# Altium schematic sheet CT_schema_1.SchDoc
size 381 x 258 mm
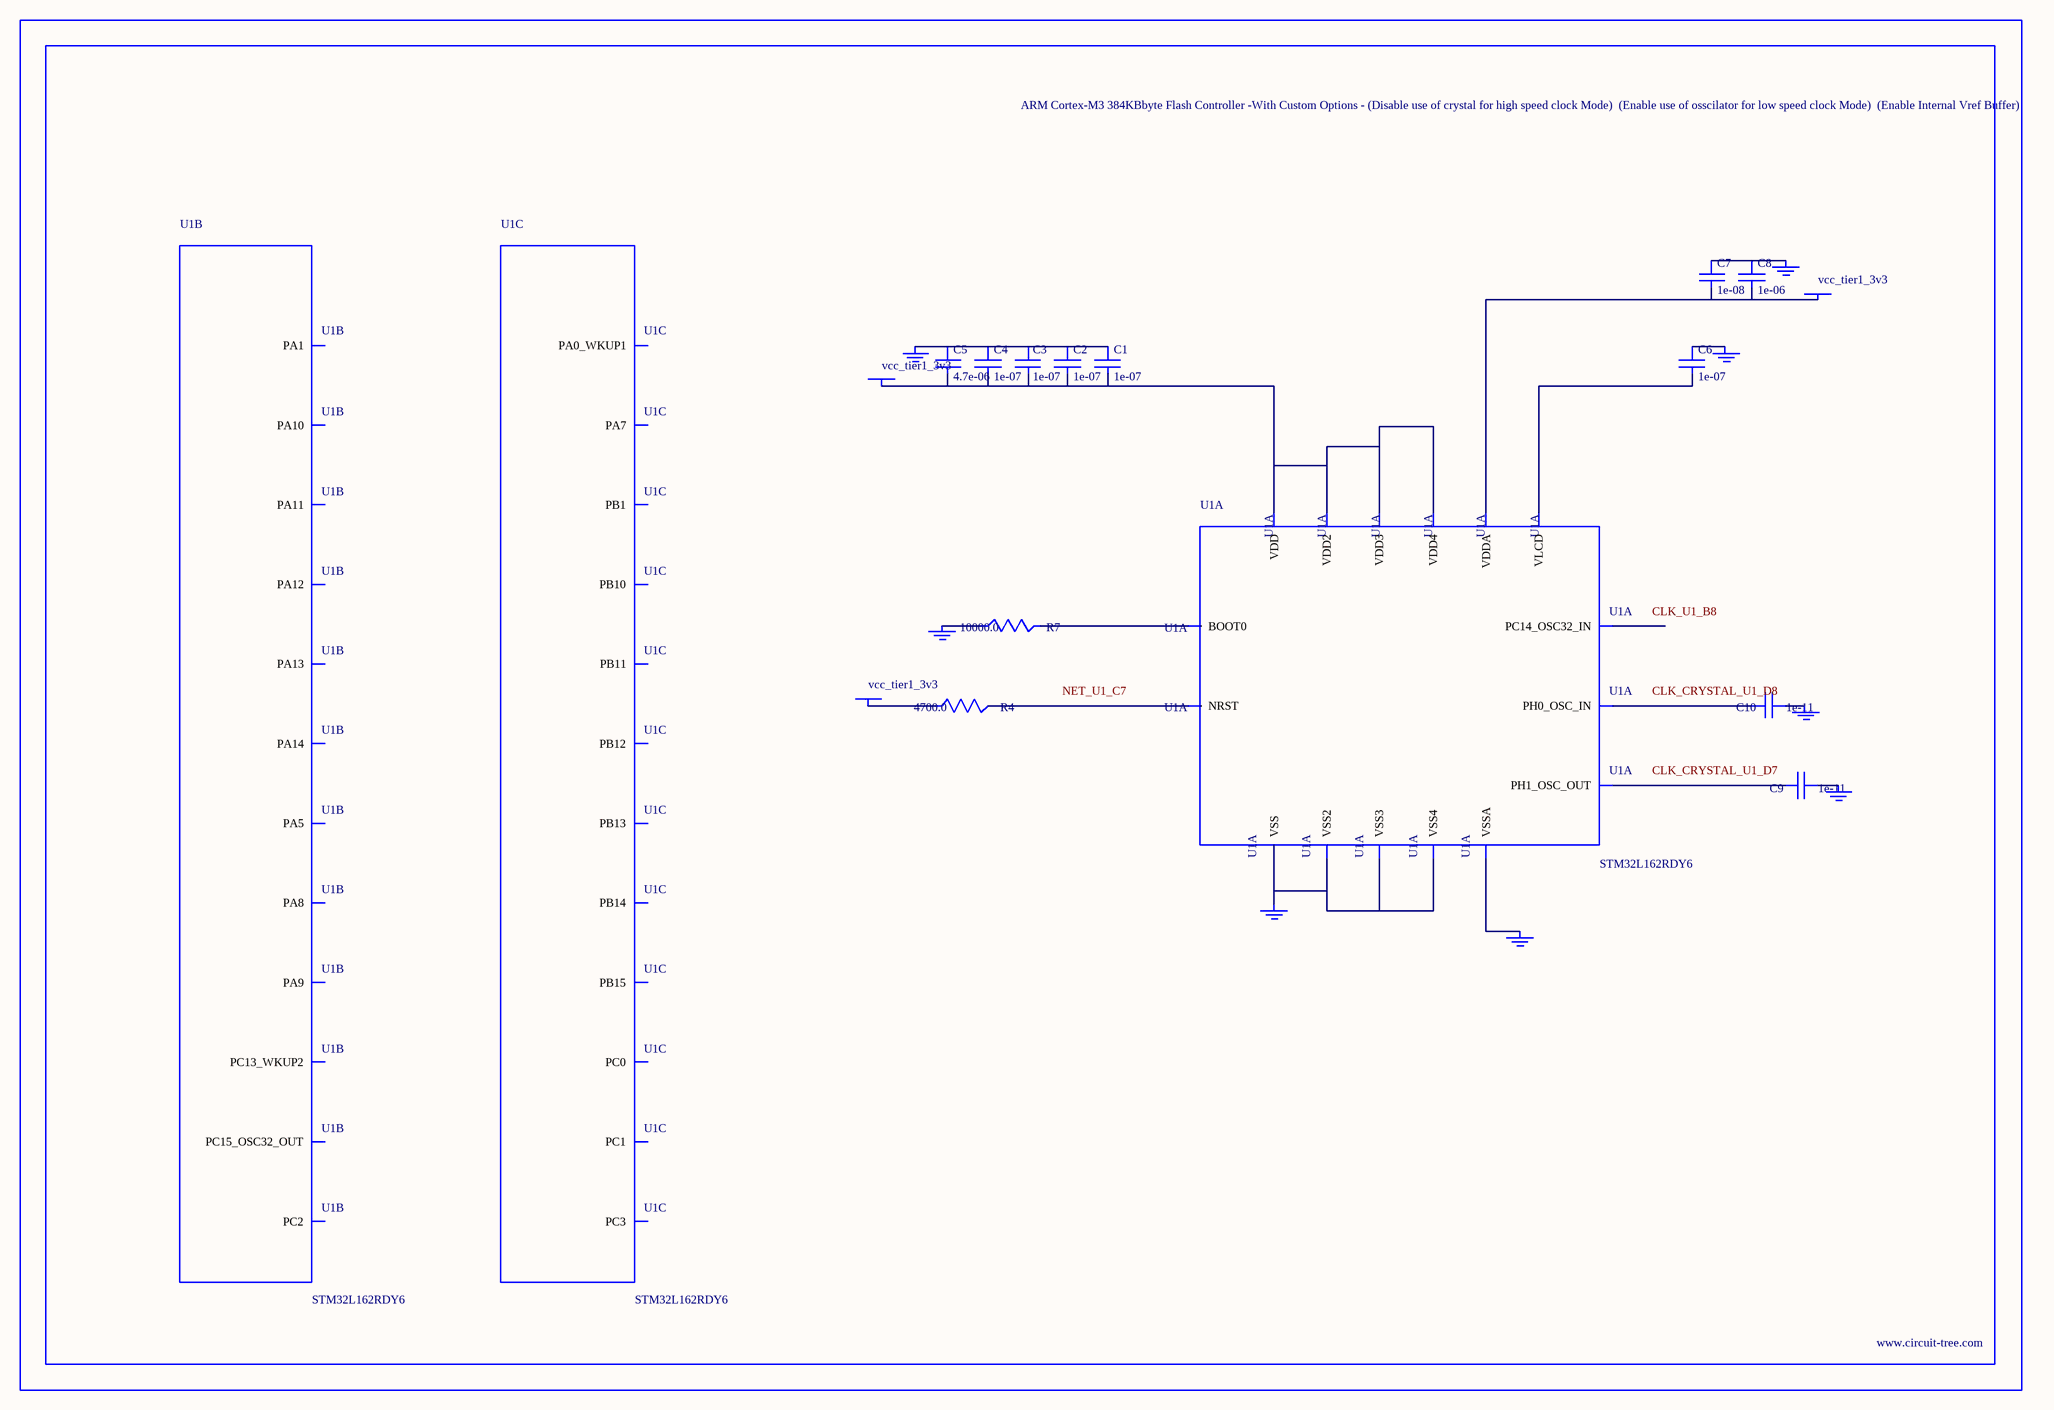
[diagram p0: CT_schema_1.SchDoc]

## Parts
BORDER0  (no value)
C1  1e-07  [C0603]
C2  1e-07  [C0603]
C3  1e-07  [C0603]
C4  1e-07  [C0603]
C5  4.7e-06  [C0603]
C6  1e-07  [C0603]
C7  1e-08  [C0603]
C8  1e-06  [C0603]
C9  1e-11  [C0402]
C10  1e-11  [C0402]
GND_INSTANCE_0_0  (no value)
GND_INSTANCE_0_1  (no value)
GND_INSTANCE_0_2  (no value)
GND_INSTANCE_0_3  (no value)
GND_INSTANCE_0_4  (no value)
GND_INSTANCE_0_5  (no value)
GND_INSTANCE_0_6  (no value)
GND_INSTANCE_0_7  (no value)
POWER_INSTANCE_0_0  vcc_tier1_3v3
POWER_INSTANCE_0_1  vcc_tier1_3v3
POWER_INSTANCE_0_2  vcc_tier1_3v3
R4  4700.0  [R0603]
R7  10000.0  [R0603]
U1  STM32L162RDY6  [WLCSP64]  (parts A,B,C of 6)

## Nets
NetC1_1: C1.1 C2.1 C3.1 C4.1 C5.1 GND_INSTANCE_0_0.0(GND)
NetC1_2: C1.2 C2.2 C3.2 C4.2 C5.2 POWER_INSTANCE_0_0.0(PWR) U1.A1(VDD) U1.A8(VDD2) U1.G6(VDD3) U1.H1(VDD4)
NetC6_1: C6.1 GND_INSTANCE_0_1.0(GND)
NetC6_2: C6.2 U1.C6(VLCD)
NetC7_1: C7.1 C8.1 GND_INSTANCE_0_3.0(GND)
NetC7_2: C7.2 C8.2 POWER_INSTANCE_0_1.0(PWR) U1.G8(VDDA)
NetC9_1: C9.1 GND_INSTANCE_0_4.0(GND)
NetC9_2: C9.2 U1.D7(PH1_OSC_OUT)
NetC10_1: C10.1 GND_INSTANCE_0_5.0(GND)
NetC10_2: C10.2 U1.D8(PH0_OSC_IN)
NetGND_INSTANCE_0_2_0: GND_INSTANCE_0_2.0(GND) R7.1
NetGND_INSTANCE_0_6_0: GND_INSTANCE_0_6.0(GND) U1.E7(VSSA)
NetGND_INSTANCE_0_7_0: GND_INSTANCE_0_7.0(GND) U1.A7(VSS) U1.B1(VSS2) U1.F5(VSS3) U1.H2(VSS4)
NetPOWER_INSTANCE_0_2_0: POWER_INSTANCE_0_2.0(PWR) R4.1
NetR4_2: R4.2 U1.C7(NRST)
NetR7_2: R7.2 U1.A6(BOOT0)

Not connected (* = marked no-connect by the designer): U1 B2(PA14) B7(PC15_OSC32_OUT) B8(PC14_OSC32_IN) C1(PA11) C2(PA12) C8(PC13_WKUP2) D2(PA9) D3(PA10) D4(PA13) D6(PC2) E4(PA8) E5(PA5) E6(PA1) E8(PC0) F1(PB15) F2(PB14) F3(PB11) F4(PB1) F6(PA0_WKUP1) F7(PC3) F8(PC1) G1(PB13) G2(PB12) G3(PB10) G4(PA7)

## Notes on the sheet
- Labels drawn without touching a wire or pin: CLK_CRYSTAL_U1_D7, CLK_CRYSTAL_U1_D8, CLK_U1_B8, NET_U1_C7

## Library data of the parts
BORDER0 = BORDER_PAGE0
C1-C4 C6 = 06035C104K4Z2A
C5 = GRM188R6YA475KE15D
C7 = 06035C103K4Z2A
C8 = C0603C105K3RACTU
C9 C10 = C0402C100K3GACTU
GND_INSTANCE_0_0-GND_INSTANCE_0_7 = GND
POWER_INSTANCE_0_0-POWER_INSTANCE_0_2 = PWR
R4 = RC0603JR-074K7L
R7 = RC0603JR-0710KL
